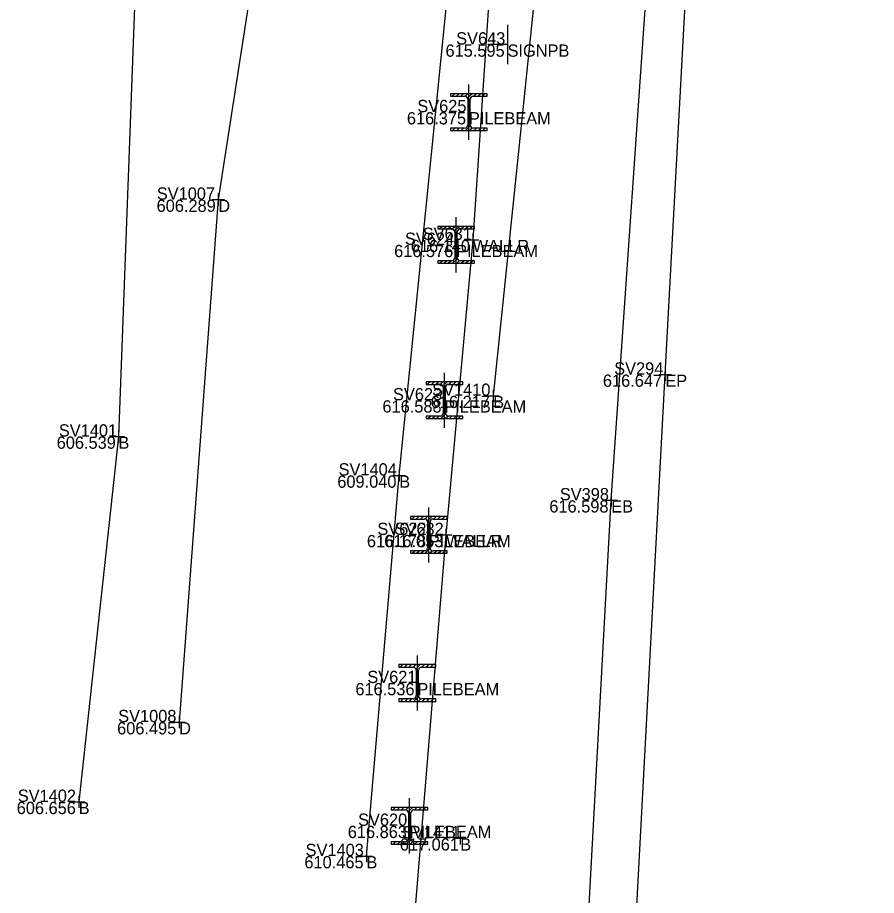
# Model space of a CAD drawing. Extents: x -2 to 1979875, y -2 to 232027.
# Drawn here: x 1978711.89 to 1978746.98, y 230841.86 to 230877.73 of the extents above; entities that cross this region are included whole.
import ezdxf

# ---------------------------------------------------------------- set-up
doc = ezdxf.new("R2010")
doc.units = 0
for name, color, linetype in [('_CIVIL_CONSTRUCTION', 7, 'Continuous'), ('DR_X_Ditch', 7, 'Continuous'), ('GE_P_Alignment', 7, 'Continuous'), ('GE_X_Alignment', 7, 'Continuous'), ('GE_X_Alignment_1000_Stations', 7, 'Continuous'), ('GE_X_Alignment_100_Curve_Data', 7, 'Continuous'), ('GE_X_Alignment_100_Stations', 7, 'Continuous'), ('GE_X_Alignment_500_Stations', 7, 'Continuous'), ('GT_X_Piling_Cells', 7, 'Continuous'), ('RD_X_Wall', 7, 'Continuous'), ('SC_Scratch1', 7, 'Continuous')]:
    doc.layers.add(name, color=color, linetype=linetype)

msp = doc.modelspace()

# ---------------------------------------------------------------- linework, layer by layer
at = {"layer": 'DR_X_Ditch'}
msp.add_lwpolyline([(1978733.264, 231097.158), (1978735.128, 231079.112), (1978735.097, 231064.293), (1978734.184, 231049.994), (1978733.773, 231035.566), (1978732.893, 231018.897), (1978731.992, 231001.991), (1978730.626, 230987.513), (1978729.316, 230971.664), (1978727.468, 230954.507), (1978726.296, 230939.503), (1978725.797, 230924.283), (1978724.583, 230908.429), (1978722.973, 230895.664), (1978722.268, 230884.362), (1978720.091, 230870.29), (1978718.491, 230848.943)], dxfattribs=at)
at = {"layer": 'GE_P_Alignment'}
msp.add_line((1978729.976, 230844.196), (1978729.976, 230844.196), dxfattribs=at)
for points in [[(1978729.881, 231097.662), (1978730.051, 231075.737), (1978730.728, 231052.356), (1978729.531, 231028.266), (1978727.279, 231001.039), (1978725.505, 230975.645), (1978723.96, 230951.153), (1978722.361, 230925.032), (1978720.121, 230901.226), (1978716.683, 230878.537), (1978716.008, 230860.612), (1978714.386, 230845.686)], [(1978726.144, 230843.471), (1978727.484, 230859.02), (1978729.675, 230880.83), (1978730.978, 230887.347), (1978732.118, 230889.086), (1978733.962, 230888.148), (1978733.593, 230884.241), (1978731.323, 230862.276)]]:
    msp.add_lwpolyline(points, dxfattribs=at)
at = {"layer": 'GE_X_Alignment_1000_Stations'}
msp.add_lwpolyline([(1978772.336, 230656.843), (1978763.559, 230673.456), (1978754.964, 230693.186), (1978747.098, 230715.323), (1978742.189, 230735.369), (1978738.656, 230754.308), (1978736.533, 230775.816), (1978735.988, 230798.596), (1978736.151, 230819.454), (1978737.13, 230840.16), (1978738.357, 230863.144), (1978739.649, 230887.098), (1978741.331, 230908.702), (1978742.827, 230930.869), (1978744.275, 230952.773), (1978745.794, 230976.041), (1978747.11, 230998.611), (1978748.464, 231019.612), (1978749.988, 231043.472)], dxfattribs=at)
at = {"layer": 'GE_X_Alignment_100_Curve_Data'}
for p, q in [((1978719.841, 230870.29), (1978720.341, 230870.29)), ((1978720.091, 230870.54), (1978720.091, 230870.04)), ((1978720.091, 230870.29), (1978720.091, 230870.29)), ((1978730.487, 230868.896), (1978730.487, 230868.396)), ((1978730.237, 230868.646), (1978730.737, 230868.646)), ((1978730.487, 230868.646), (1978730.487, 230868.646)), ((1978738.357, 230863.394), (1978738.357, 230862.894)), ((1978738.107, 230863.144), (1978738.607, 230863.144)), ((1978738.357, 230863.144), (1978738.357, 230863.144)), ((1978731.323, 230862.526), (1978731.323, 230862.026)), ((1978731.073, 230862.276), (1978731.573, 230862.276)), ((1978731.323, 230862.276), (1978731.323, 230862.276)), ((1978715.758, 230860.612), (1978716.258, 230860.612)), ((1978716.008, 230860.862), (1978716.008, 230860.362)), ((1978716.008, 230860.612), (1978716.008, 230860.612)), ((1978727.484, 230859.27), (1978727.484, 230858.77)), ((1978727.234, 230859.02), (1978727.734, 230859.02)), ((1978727.484, 230859.02), (1978727.484, 230859.02)), ((1978736.148, 230858.257), (1978736.148, 230857.757)), ((1978735.898, 230858.007), (1978736.398, 230858.007)), ((1978736.148, 230858.007), (1978736.148, 230858.007)), ((1978729.145, 230856.593), (1978729.645, 230856.593)), ((1978729.395, 230856.843), (1978729.395, 230856.343)), ((1978729.395, 230856.593), (1978729.395, 230856.593)), ((1978718.491, 230849.193), (1978718.491, 230848.693)), ((1978718.241, 230848.943), (1978718.741, 230848.943)), ((1978718.491, 230848.943), (1978718.491, 230848.943)), ((1978714.386, 230845.936), (1978714.386, 230845.436)), ((1978714.136, 230845.686), (1978714.636, 230845.686)), ((1978714.386, 230845.686), (1978714.386, 230845.686)), ((1978729.976, 230844.446), (1978729.976, 230843.946)), ((1978729.726, 230844.196), (1978730.226, 230844.196)), ((1978729.976, 230844.196), (1978729.976, 230844.196)), ((1978726.144, 230843.721), (1978726.144, 230843.221)), ((1978725.894, 230843.471), (1978726.394, 230843.471)), ((1978726.144, 230843.471), (1978726.144, 230843.471))]:
    msp.add_line(p, q, dxfattribs=at)
at = {"layer": 'GE_X_Alignment_500_Stations'}
for p, q in [((1978731.91, 230877.43), (1978731.91, 230875.83)), ((1978731.91, 230876.63), (1978731.11, 230876.63))]:
    msp.add_line(p, q, dxfattribs=at)
at = {"layer": 'GT_X_Piling_Cells'}
for p, q in [((1978730.332, 230872.74), (1978730.332, 230874.99)), ((1978731.082, 230874.615), (1978729.582, 230874.615)), ((1978729.582, 230874.615), (1978729.582, 230874.515)), ((1978729.582, 230874.515), (1978730.157, 230874.515)), ((1978729.645, 230874.515), (1978729.745, 230874.615)), ((1978729.821, 230874.515), (1978729.921, 230874.615)), ((1978729.998, 230874.515), (1978730.098, 230874.615)), ((1978730.174, 230874.514), (1978730.275, 230874.615)), ((1978730.273, 230874.436), (1978730.452, 230874.615)), ((1978730.507, 230874.515), (1978731.082, 230874.515)), ((1978730.528, 230874.515), (1978730.628, 230874.615)), ((1978730.705, 230874.515), (1978730.805, 230874.615)), ((1978730.882, 230874.515), (1978730.982, 230874.615)), ((1978731.059, 230874.515), (1978731.082, 230874.538)), ((1978731.082, 230874.515), (1978731.082, 230874.615)), ((1978730.282, 230874.39), (1978730.282, 230873.34)), ((1978730.282, 230874.269), (1978730.382, 230874.369)), ((1978730.282, 230874.092), (1978730.382, 230874.192)), ((1978730.382, 230873.34), (1978730.382, 230874.39)), ((1978730.282, 230873.915), (1978730.382, 230874.015)), ((1978730.282, 230873.738), (1978730.382, 230873.838)), ((1978730.332, 230873.865), (1978730.332, 230873.865)), ((1978730.282, 230873.561), (1978730.382, 230873.661)), ((1978730.282, 230873.385), (1978730.382, 230873.485)), ((1978730.157, 230873.215), (1978729.582, 230873.215)), ((1978729.582, 230873.215), (1978729.582, 230873.115)), ((1978729.582, 230873.115), (1978731.082, 230873.115)), ((1978729.659, 230873.115), (1978729.759, 230873.215)), ((1978729.836, 230873.115), (1978729.936, 230873.215)), ((1978730.012, 230873.115), (1978730.112, 230873.215)), ((1978730.189, 230873.115), (1978730.385, 230873.311)), ((1978730.366, 230873.115), (1978730.471, 230873.22)), ((1978731.082, 230873.215), (1978730.507, 230873.215)), ((1978730.543, 230873.115), (1978730.643, 230873.215)), ((1978730.719, 230873.115), (1978730.819, 230873.215)), ((1978730.896, 230873.115), (1978730.996, 230873.215)), ((1978731.073, 230873.115), (1978731.082, 230873.124)), ((1978731.082, 230873.115), (1978731.082, 230873.215)), ((1978729.808, 230867.318), (1978729.808, 230869.568)), ((1978730.558, 230869.193), (1978729.058, 230869.193)), ((1978729.058, 230869.193), (1978729.058, 230869.093)), ((1978729.121, 230869.093), (1978729.221, 230869.193)), ((1978729.297, 230869.093), (1978729.397, 230869.193)), ((1978729.474, 230869.093), (1978729.574, 230869.193)), ((1978729.65, 230869.092), (1978729.751, 230869.193)), ((1978729.749, 230869.014), (1978729.928, 230869.193)), ((1978730.004, 230869.093), (1978730.104, 230869.193)), ((1978730.181, 230869.093), (1978730.281, 230869.193)), ((1978730.358, 230869.093), (1978730.458, 230869.193)), ((1978730.558, 230869.093), (1978730.558, 230869.193)), ((1978729.058, 230869.093), (1978729.633, 230869.093)), ((1978729.758, 230868.968), (1978729.758, 230867.918)), ((1978729.758, 230868.847), (1978729.858, 230868.947)), ((1978729.858, 230867.918), (1978729.858, 230868.968)), ((1978729.983, 230869.093), (1978730.558, 230869.093)), ((1978730.535, 230869.093), (1978730.558, 230869.116)), ((1978729.758, 230868.67), (1978729.858, 230868.77)), ((1978729.758, 230868.493), (1978729.858, 230868.593)), ((1978729.758, 230868.316), (1978729.858, 230868.416)), ((1978729.808, 230868.443), (1978729.808, 230868.443)), ((1978729.758, 230868.139), (1978729.858, 230868.239)), ((1978729.758, 230867.963), (1978729.858, 230868.063)), ((1978729.633, 230867.793), (1978729.058, 230867.793)), ((1978729.058, 230867.793), (1978729.058, 230867.693)), ((1978729.135, 230867.693), (1978729.235, 230867.793)), ((1978729.312, 230867.693), (1978729.412, 230867.793)), ((1978729.488, 230867.693), (1978729.588, 230867.793)), ((1978729.665, 230867.693), (1978729.861, 230867.889)), ((1978729.842, 230867.693), (1978729.947, 230867.798)), ((1978730.558, 230867.793), (1978729.983, 230867.793)), ((1978730.019, 230867.693), (1978730.119, 230867.793)), ((1978730.195, 230867.693), (1978730.295, 230867.793)), ((1978730.372, 230867.693), (1978730.472, 230867.793)), ((1978730.549, 230867.693), (1978730.558, 230867.702)), ((1978730.558, 230867.693), (1978730.558, 230867.793)), ((1978729.058, 230867.693), (1978730.558, 230867.693)), ((1978729.328, 230860.967), (1978729.328, 230863.217)), ((1978730.078, 230862.842), (1978728.578, 230862.842)), ((1978728.578, 230862.842), (1978728.578, 230862.742)), ((1978728.578, 230862.742), (1978729.153, 230862.742)), ((1978728.641, 230862.742), (1978728.741, 230862.842)), ((1978728.817, 230862.742), (1978728.917, 230862.842)), ((1978728.994, 230862.742), (1978729.094, 230862.842)), ((1978729.17, 230862.741), (1978729.271, 230862.842)), ((1978729.269, 230862.663), (1978729.448, 230862.842)), ((1978729.503, 230862.742), (1978730.078, 230862.742)), ((1978729.524, 230862.742), (1978729.624, 230862.842)), ((1978729.701, 230862.742), (1978729.801, 230862.842)), ((1978729.878, 230862.742), (1978729.978, 230862.842)), ((1978730.055, 230862.742), (1978730.078, 230862.765)), ((1978730.078, 230862.742), (1978730.078, 230862.842)), ((1978729.278, 230862.617), (1978729.278, 230861.567)), ((1978729.278, 230862.496), (1978729.378, 230862.596)), ((1978729.278, 230862.319), (1978729.378, 230862.419)), ((1978729.378, 230861.567), (1978729.378, 230862.617)), ((1978729.278, 230862.142), (1978729.378, 230862.242)), ((1978729.278, 230861.965), (1978729.378, 230862.065)), ((1978729.328, 230862.092), (1978729.328, 230862.092)), ((1978729.278, 230861.788), (1978729.378, 230861.888)), ((1978729.278, 230861.612), (1978729.378, 230861.712)), ((1978729.153, 230861.442), (1978728.578, 230861.442)), ((1978728.578, 230861.442), (1978728.578, 230861.342)), ((1978728.578, 230861.342), (1978730.078, 230861.342)), ((1978728.655, 230861.342), (1978728.755, 230861.442)), ((1978728.832, 230861.342), (1978728.932, 230861.442)), ((1978729.008, 230861.342), (1978729.108, 230861.442)), ((1978729.185, 230861.342), (1978729.381, 230861.538)), ((1978729.362, 230861.342), (1978729.467, 230861.447)), ((1978730.078, 230861.442), (1978729.503, 230861.442)), ((1978729.539, 230861.342), (1978729.639, 230861.442)), ((1978729.715, 230861.342), (1978729.815, 230861.442)), ((1978729.892, 230861.342), (1978729.992, 230861.442)), ((1978730.069, 230861.342), (1978730.078, 230861.351)), ((1978730.078, 230861.342), (1978730.078, 230861.442)), ((1978728.692, 230855.465), (1978728.692, 230857.715)), ((1978729.442, 230857.34), (1978727.942, 230857.34)), ((1978727.942, 230857.34), (1978727.942, 230857.24)), ((1978728.005, 230857.24), (1978728.105, 230857.34)), ((1978728.181, 230857.24), (1978728.281, 230857.34)), ((1978728.358, 230857.24), (1978728.458, 230857.34)), ((1978728.534, 230857.239), (1978728.635, 230857.34)), ((1978728.633, 230857.161), (1978728.812, 230857.34)), ((1978728.888, 230857.24), (1978728.988, 230857.34)), ((1978729.065, 230857.24), (1978729.165, 230857.34)), ((1978729.242, 230857.24), (1978729.342, 230857.34)), ((1978729.442, 230857.24), (1978729.442, 230857.34)), ((1978727.942, 230857.24), (1978728.517, 230857.24)), ((1978728.642, 230857.115), (1978728.642, 230856.065)), ((1978728.642, 230856.994), (1978728.742, 230857.094)), ((1978728.742, 230856.065), (1978728.742, 230857.115)), ((1978728.867, 230857.24), (1978729.442, 230857.24)), ((1978729.419, 230857.24), (1978729.442, 230857.263)), ((1978728.642, 230856.817), (1978728.742, 230856.917)), ((1978728.642, 230856.64), (1978728.742, 230856.74)), ((1978728.692, 230856.59), (1978728.692, 230856.59)), ((1978728.642, 230856.463), (1978728.742, 230856.563)), ((1978728.642, 230856.286), (1978728.742, 230856.386)), ((1978728.517, 230855.94), (1978727.942, 230855.94)), ((1978727.942, 230855.94), (1978727.942, 230855.84)), ((1978728.019, 230855.84), (1978728.119, 230855.94)), ((1978728.196, 230855.84), (1978728.296, 230855.94)), ((1978728.372, 230855.84), (1978728.472, 230855.94)), ((1978728.549, 230855.84), (1978728.745, 230856.036)), ((1978728.642, 230856.11), (1978728.742, 230856.21)), ((1978728.726, 230855.84), (1978728.831, 230855.945)), ((1978729.442, 230855.94), (1978728.867, 230855.94)), ((1978728.903, 230855.84), (1978729.003, 230855.94)), ((1978729.079, 230855.84), (1978729.179, 230855.94)), ((1978729.256, 230855.84), (1978729.356, 230855.94)), ((1978729.442, 230855.84), (1978729.442, 230855.94)), ((1978727.942, 230855.84), (1978729.442, 230855.84)), ((1978729.433, 230855.84), (1978729.442, 230855.849)), ((1978728.224, 230849.416), (1978728.224, 230851.666)), ((1978728.974, 230851.291), (1978727.474, 230851.291)), ((1978727.474, 230851.291), (1978727.474, 230851.191)), ((1978727.537, 230851.191), (1978727.637, 230851.291)), ((1978727.713, 230851.191), (1978727.813, 230851.291)), ((1978727.89, 230851.191), (1978727.99, 230851.291)), ((1978728.066, 230851.19), (1978728.167, 230851.291)), ((1978728.165, 230851.112), (1978728.344, 230851.291)), ((1978728.42, 230851.191), (1978728.52, 230851.291)), ((1978728.597, 230851.191), (1978728.697, 230851.291)), ((1978728.774, 230851.191), (1978728.874, 230851.291)), ((1978728.951, 230851.191), (1978728.974, 230851.214)), ((1978728.974, 230851.191), (1978728.974, 230851.291)), ((1978727.474, 230851.191), (1978728.049, 230851.191)), ((1978728.174, 230851.066), (1978728.174, 230850.016)), ((1978728.174, 230850.945), (1978728.274, 230851.045)), ((1978728.174, 230850.768), (1978728.274, 230850.868)), ((1978728.274, 230850.016), (1978728.274, 230851.066)), ((1978728.399, 230851.191), (1978728.974, 230851.191)), ((1978728.174, 230850.591), (1978728.274, 230850.691)), ((1978728.174, 230850.414), (1978728.274, 230850.514)), ((1978728.224, 230850.541), (1978728.224, 230850.541)), ((1978728.174, 230850.237), (1978728.274, 230850.337)), ((1978728.174, 230850.061), (1978728.274, 230850.161)), ((1978728.049, 230849.891), (1978727.474, 230849.891)), ((1978727.474, 230849.891), (1978727.474, 230849.791)), ((1978727.474, 230849.791), (1978728.974, 230849.791)), ((1978727.551, 230849.791), (1978727.651, 230849.891)), ((1978727.728, 230849.791), (1978727.828, 230849.891)), ((1978727.904, 230849.791), (1978728.004, 230849.891)), ((1978728.081, 230849.791), (1978728.277, 230849.987)), ((1978728.258, 230849.791), (1978728.363, 230849.896)), ((1978728.974, 230849.891), (1978728.399, 230849.891)), ((1978728.435, 230849.791), (1978728.535, 230849.891)), ((1978728.611, 230849.791), (1978728.711, 230849.891)), ((1978728.788, 230849.791), (1978728.888, 230849.891)), ((1978728.965, 230849.791), (1978728.974, 230849.8)), ((1978728.974, 230849.791), (1978728.974, 230849.891)), ((1978727.906, 230843.582), (1978727.906, 230845.832)), ((1978728.656, 230845.457), (1978727.156, 230845.457)), ((1978727.156, 230845.457), (1978727.156, 230845.357)), ((1978727.156, 230845.357), (1978727.731, 230845.357)), ((1978727.219, 230845.357), (1978727.319, 230845.457)), ((1978727.395, 230845.357), (1978727.495, 230845.457)), ((1978727.572, 230845.357), (1978727.672, 230845.457)), ((1978727.748, 230845.356), (1978727.849, 230845.457)), ((1978727.847, 230845.278), (1978728.026, 230845.457)), ((1978727.856, 230845.232), (1978727.856, 230844.182)), ((1978727.856, 230845.111), (1978727.956, 230845.211)), ((1978727.956, 230844.182), (1978727.956, 230845.232)), ((1978728.081, 230845.357), (1978728.656, 230845.357)), ((1978728.102, 230845.357), (1978728.202, 230845.457)), ((1978728.279, 230845.357), (1978728.379, 230845.457)), ((1978728.456, 230845.357), (1978728.556, 230845.457)), ((1978728.633, 230845.357), (1978728.656, 230845.38)), ((1978728.656, 230845.357), (1978728.656, 230845.457)), ((1978727.856, 230844.934), (1978727.956, 230845.034)), ((1978727.856, 230844.757), (1978727.956, 230844.857)), ((1978727.856, 230844.58), (1978727.956, 230844.68)), ((1978727.856, 230844.403), (1978727.956, 230844.503)), ((1978727.906, 230844.707), (1978727.906, 230844.707)), ((1978727.731, 230844.057), (1978727.156, 230844.057)), ((1978727.156, 230844.057), (1978727.156, 230843.957)), ((1978727.233, 230843.957), (1978727.333, 230844.057)), ((1978727.41, 230843.957), (1978727.51, 230844.057)), ((1978727.586, 230843.957), (1978727.686, 230844.057)), ((1978727.763, 230843.957), (1978727.959, 230844.153)), ((1978727.856, 230844.227), (1978727.956, 230844.327)), ((1978727.94, 230843.957), (1978728.045, 230844.062)), ((1978728.656, 230844.057), (1978728.081, 230844.057)), ((1978728.117, 230843.957), (1978728.217, 230844.057)), ((1978728.293, 230843.957), (1978728.393, 230844.057)), ((1978728.47, 230843.957), (1978728.57, 230844.057)), ((1978728.656, 230843.957), (1978728.656, 230844.057)), ((1978727.156, 230843.957), (1978728.656, 230843.957)), ((1978728.647, 230843.957), (1978728.656, 230843.966))]:
    msp.add_line(p, q, dxfattribs=at)
for centre, start, end in [((1978730.157, 230874.39), 0, 90), ((1978730.507, 230874.39), 90, 180), ((1978730.157, 230873.34), 270, 0), ((1978730.507, 230873.34), 180, 270), ((1978729.633, 230868.968), 0, 90), ((1978729.983, 230868.968), 90, 180), ((1978729.633, 230867.918), 270, 0), ((1978729.983, 230867.918), 180, 270), ((1978729.153, 230862.617), 0, 90), ((1978729.503, 230862.617), 90, 180), ((1978729.153, 230861.567), 270, 0), ((1978729.503, 230861.567), 180, 270), ((1978728.517, 230857.115), 0, 90), ((1978728.867, 230857.115), 90, 180), ((1978728.517, 230856.065), 270, 0), ((1978728.867, 230856.065), 180, 270), ((1978728.049, 230851.066), 0, 90), ((1978728.399, 230851.066), 90, 180), ((1978728.049, 230850.016), 270, 0), ((1978728.399, 230850.016), 180, 270), ((1978727.731, 230845.232), 0, 90), ((1978728.081, 230845.232), 90, 180), ((1978727.731, 230844.182), 270, 0), ((1978728.081, 230844.182), 180, 270)]:
    msp.add_arc(centre, 0.125, start, end, dxfattribs=at)
at = {"layer": 'RD_X_Wall'}
msp.add_lwpolyline([(1978732.056, 230886.781), (1978731.746, 230883.073), (1978731.431, 230882.716), (1978730.487, 230868.646), (1978729.395, 230856.593), (1978727.895, 230838.391), (1978726.998, 230826.855), (1978726.244, 230816.011), (1978726.384, 230805.15), (1978727.259, 230789.767), (1978727.515, 230778.19), (1978728.731, 230764.777), (1978729.78, 230755.535)], dxfattribs=at)
at = {"layer": 'SC_Scratch1'}
msp.add_lwpolyline([(1978770.288, 230655.73), (1978760.891, 230674.584), (1978752.193, 230695.227), (1978744.942, 230716.175), (1978738.905, 230740.874), (1978735.553, 230763.886), (1978733.918, 230787.98), (1978733.819, 230809.219), (1978734.805, 230833.453), (1978736.148, 230858.007), (1978737.85, 230882.597), (1978739.105, 230905.756), (1978740.693, 230929.953), (1978742.419, 230953.633), (1978743.494, 230976.312), (1978745.216, 230999.029), (1978746.767, 231023.392)], dxfattribs=at)

# ---------------------------------------------------------------- texts
at = {"layer": '_CIVIL_CONSTRUCTION'}
for s, p in [('615.595', (1978729.375, 230876.13)), ('616.375', (1978727.797, 230873.365)), ('606.289', (1978717.57, 230869.79)), ('616.576', (1978727.276, 230867.943)), ('616.140', (1978727.957, 230868.146)), ('616.647', (1978735.806, 230862.644)), ('616.588', (1978726.798, 230861.592)), ('616.217', (1978728.772, 230861.776)), ('606.539', (1978713.487, 230860.112)), ('609.040', (1978724.954, 230858.52)), ('616.598', (1978733.618, 230857.507)), ('616.178', (1978726.162, 230856.09)), ('616.053', (1978726.87, 230856.093)), ('616.536', (1978725.692, 230850.041)), ('606.495', (1978715.956, 230848.443)), ('606.656', (1978711.854, 230845.186)), ('616.863', (1978725.381, 230844.207)), ('617.061', (1978727.506, 230843.696)), ('610.465', (1978723.609, 230842.971))]:
    msp.add_text(s, height=0.5, dxfattribs=at).set_placement(p)
at = {"layer": 'GE_X_Alignment'}
for s, p in [('SV643', (1978729.812, 230876.63)), ('SV625', (1978728.223, 230873.865)), ('SV1007', (1978717.578, 230870.29)), ('SV631', (1978728.444, 230868.646)), ('SV624', (1978727.719, 230868.443)), ('SV294', (1978736.268, 230863.144)), ('SV1410', (1978728.831, 230862.276)), ('SV623', (1978727.23, 230862.092)), ('SV1401', (1978713.576, 230860.612)), ('SV1404', (1978725.007, 230859.02)), ('SV398', (1978734.045, 230858.007)), ('SV622', (1978726.591, 230856.59)), ('SV632', (1978727.294, 230856.593)), ('SV621', (1978726.181, 230850.541)), ('SV1008', (1978716, 230848.943)), ('SV1402', (1978711.896, 230845.686)), ('SV620', (1978725.802, 230844.707)), ('SV1411', (1978727.596, 230844.196)), ('SV1403', (1978723.658, 230843.471))]:
    msp.add_text(s, height=0.5, dxfattribs=at).set_placement(p)
at = {"layer": 'GE_X_Alignment_100_Stations'}
for s, p in [('SIGNPB', (1978731.91, 230876.13)), ('PILEBEAM', (1978730.332, 230873.365)), ('D', (1978720.091, 230869.79)), ('PILEBEAM', (1978729.808, 230867.943)), ('WALLR', (1978730.487, 230868.146)), ('EP', (1978738.357, 230862.644)), ('PILEBEAM', (1978729.328, 230861.592)), ('B', (1978731.323, 230861.776)), ('B', (1978716.008, 230860.112)), ('B', (1978727.484, 230858.52)), ('EB', (1978736.148, 230857.507)), ('PILEBEAM', (1978728.692, 230856.09)), ('WALLR', (1978729.395, 230856.093)), ('PILEBEAM', (1978728.224, 230850.041)), ('D', (1978718.491, 230848.443)), ('B', (1978714.386, 230845.186)), ('PILEBEAM', (1978727.906, 230844.207)), ('B', (1978729.976, 230843.696)), ('B', (1978726.144, 230842.971))]:
    msp.add_text(s, height=0.5, dxfattribs=at).set_placement(p)

doc.saveas('drawing.dxf')
